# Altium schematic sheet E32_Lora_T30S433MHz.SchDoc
size A4; Organization: Altium Limited; Address1: L3, 12a Rodborough Rd; Address2: Frenchs Forest; Address3: NSW; Address4: Australia 2086
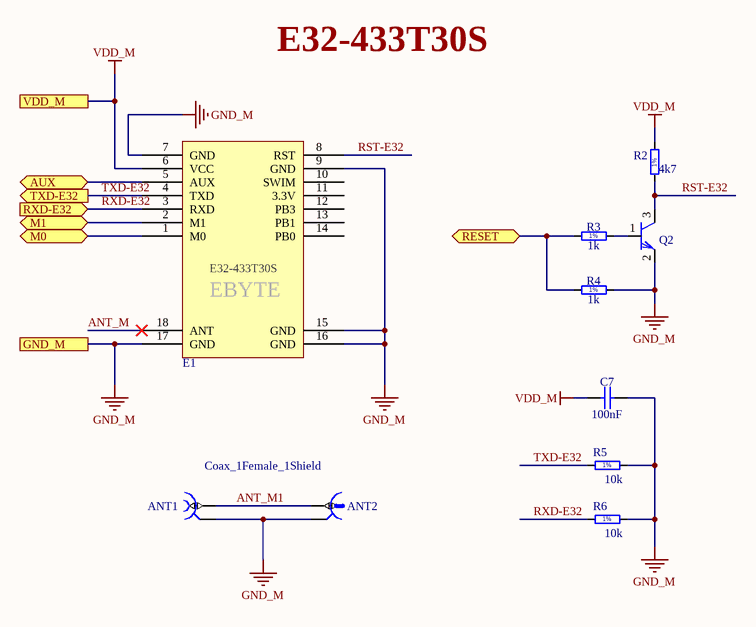
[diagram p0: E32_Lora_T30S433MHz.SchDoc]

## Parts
ANT1  Coax_1Female_1Shield  [HUBER-SUHNER_85 SMA-50-0-101/111 NE]
ANT2  U.FL  [HIROSE_U.FL-R-SMT-1(10)]  (value not drawn)
C7  100nF  [CAPC1608X87N]
E1  E32-T30S  [E32-433T30S]  (value not drawn)
Q2  C1815  [SOT23-3]  (value not drawn)
R2  4k7  [RESC1608X55N]
R3  1k  [RESC1608X55N]
R4  1k  [RESC1608X55N]
R5  10k  [RESC1608X55N]
R6  10k  [RESC1608X55N]

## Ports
AUX (bidir), GND_M, M0 (bidir), M1 (bidir), RESET (bidir), RXD-E32 (in), TXD-E32 (out), VDD_M

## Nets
GND_M: ANT1.2 ANT2.2 C7.2 E1.7(GND) E1.9(GND) E1.15(GND) E1.16(GND) E1.17(GND) Q2.2(E) R4.2 R5.2 R6.2 ; port GND_M
VDD_M: C7.1 E1.6(VCC) R2.2 ; port VDD_M
ANT_M: E1.18(ANT)
ANT_M1: ANT1.1 ANT2.1
AUX: E1.5(AUX) ; port AUX
M0: E1.1(M0) ; port M0
M1: E1.2(M1) ; port M1
RESET: R3.1 R4.1 ; port RESET
RST-E32: E1.8(RST) Q2.3(C) R2.1
RXD-E32: E1.3(RXD) R6.1 ; port RXD-E32
TXD-E32: E1.4(TXD) R5.1 ; port TXD-E32
NetQ2_1: Q2.1(B) R3.2

Not connected (* = marked no-connect by the designer): E1 10(SWIM) 11(3.3V) 12(PB3) 13(PB1) 14(PB0)

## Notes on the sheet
- E32-433T30S

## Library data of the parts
ANT1 = HUBER-SUHNER_85_SMA-50-0-101/111_NE: Part Description: SMA 50 Ohms Right Angle PCB Jack; Manufacturer: HUBER+SUHNER; Table: Miscellaneous
ANT2 = HIROSE_U.FL-R-SMT-1(10): Part Description: Up to 6GHz Ultra Small Surface Mount Male Coaxial Connectors U.FL Series; Manufacturer: HIROSE (HRS); Table: Miscellaneous
C7 = CC0603_100NF_50V_10%_X7R: Non-polarised capacitor; Part Description: SMD Multilayer Chip Ceramic Capacitor; Manufacturer: GENERIC; Manufacturer1 Part Number: 223858615649; Voltage: 50V; TC: X7R; Tolerance: ±10%; Table: Capacitors SMD
E1 = E32-433T30S: Lora Ebyte E32-T30S Module
Q2 = 2SC1815: PSpiceTemplate: Q^@REFDES %c %b %e @MODEL; Vendor: Digikey
R2 = R0603_4K7_1%_0.1W_100PPM: Resistor - 1%; Part Description: General Purpose Thick Film Chip Resistor; Manufacturer: GENERIC; Manufacturer1 Part Number: NRC06F4701TRF; Power: 0.1W; TC: ±100ppm/°C; Table: Resistors SMD
R3 R4 = R0603_1K_1%_0.1W_100PPM: Resistor - 1%; Part Description: General Purpose Thick Film Chip Resistor; Manufacturer: GENERIC; Manufacturer1 Part Number: NRC06F1001TRF; Power: 0.1W; TC: ±100ppm/°C; Table: Resistors SMD
R5 R6 = R0603_10K_1%_0.1W_100PPM: Resistor - 1%; Part Description: General Purpose Thick Film Chip Resistor; Manufacturer: GENERIC; Manufacturer1 Part Number: NRC06F1002TRF; Power: 0.1W; TC: ±100ppm/°C; Table: Resistors SMD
